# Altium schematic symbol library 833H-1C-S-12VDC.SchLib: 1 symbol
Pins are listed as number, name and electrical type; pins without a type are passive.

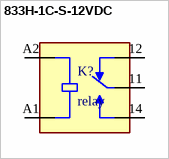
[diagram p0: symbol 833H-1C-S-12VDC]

## 833H-1C-S-12VDC
designator K?, comment relay
833H Series 10 A SPDT 12 VDC Through Hole Miniature Sugar Cube Power Relay; MF: Song Chuan; MP: 833H-1C-S-12VDC
footprint RELAY_833H-1C-S-12VDC
pins: 11 COM, 12 NC, 14 NO, A1 COIL2, A2 COIL1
